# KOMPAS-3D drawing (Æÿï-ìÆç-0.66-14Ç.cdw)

Views: Вид 1, Вид 2
Referenced files in W:\Технический отдел\КБ\Рабочая папка\КД\Экспериментальное, тех решения\Испанский датчик\: ТШП-0,66 ГЧ.cdw
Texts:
  max
  Табличка технических
  данных
  Винт М6
  Масса не более 21,5 кг
  ТШЛ-НТЗ-0,66-14 УХЛ2, Т2
  Яковлев
  Михайлов
  Морозов
  Фролова
  Пимурзин
  М.Контр.
  Трансформатор тока
  нулевой последовательности
  ТЗЛК-НТЗ-0,66-70(-100,-125,-205)-01 У2
  Габаритный чертеж
  см. табл.
  НТЗ
  НТЗ.03.14.00.00.000
  Без внутренней рамки.
Dimensions and other numbers on the sheet: 250; 205; 161; 320; 180; 318; 122; 20; 4 шт. max; 3; -7Нх15; 10; 4 отв.; 60; 136; 3х20=60; 1:2; 1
